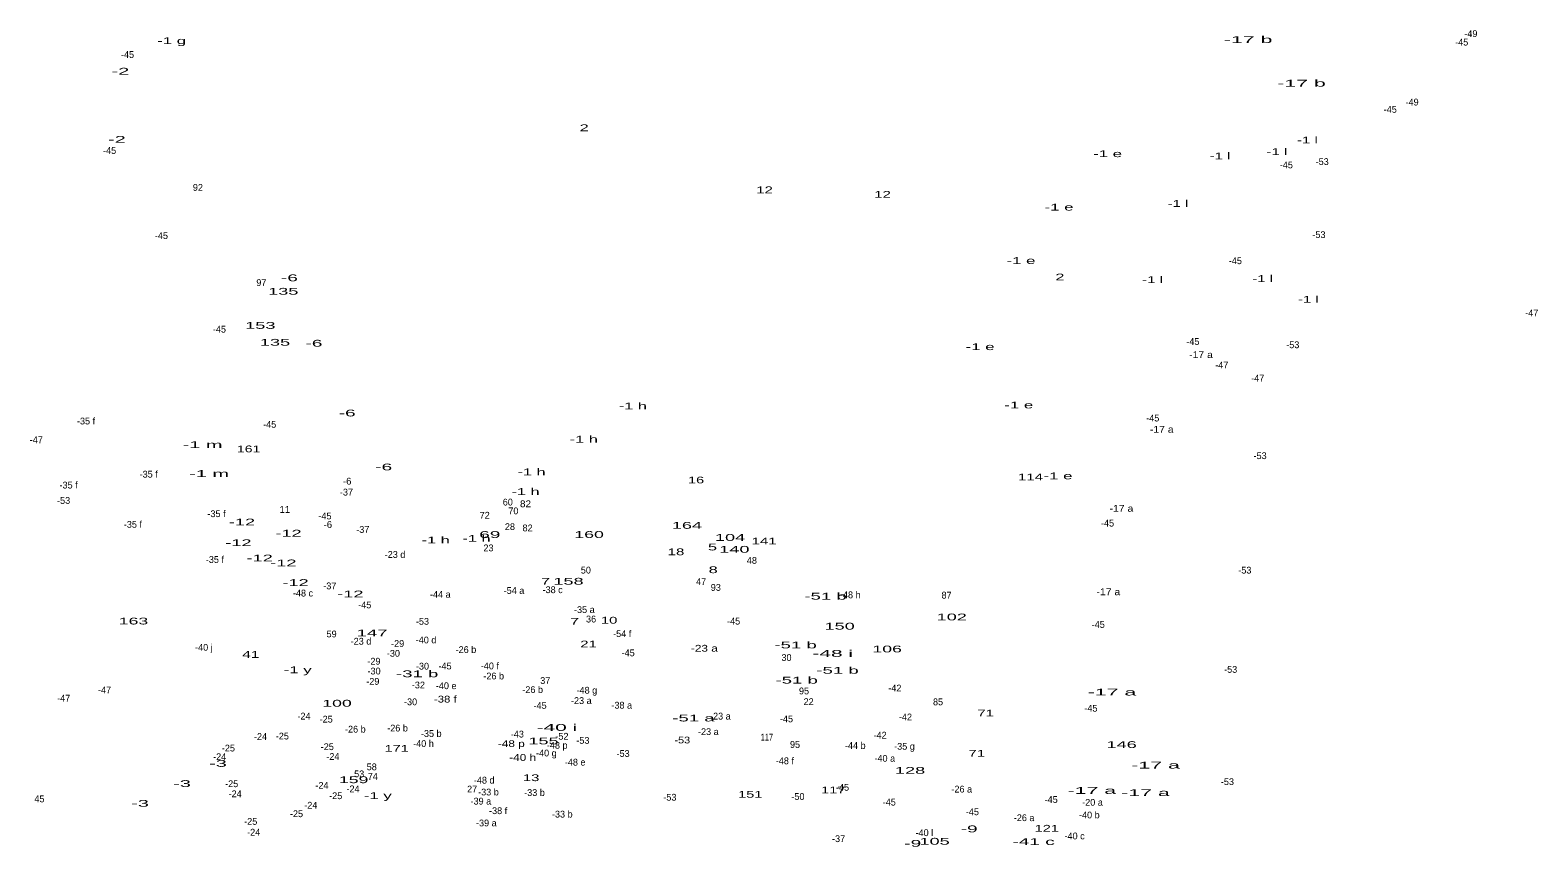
# Model space of a CAD drawing. Extents: x -668622 to -666786, y -990362 to -986505.
# Drawn here: x -667804 to -666915, y -988917 to -988436 of the extents above; entities that cross this region are included whole.
import ezdxf
from ezdxf.enums import TextEntityAlignment as Align

# ---------------------------------------------------------------- set-up
doc = ezdxf.new("R2010")
doc.units = 0
doc.header["$LTSCALE"] = 1.6
doc.layers.add('24', color=7, linetype='Continuous')

msp = doc.modelspace()

# ---------------------------------------------------------------- texts
at = {"layer": '24'}
for s, width, p in [('-1 g', 1.85, (-667720.401, -988444.19)), ('-17 b', 2.35, (-667085.535, -988443.52)), ('-2', 2.2, (-667750.564, -988462.18)), ('-17 b', 2.35, (-667054.045, -988469.23)), ('2', 1.8, (-667477.081, -988495.52)), ('-2', 2.2, (-667752.654, -988502.34)), ('-1 l', 1.65, (-667050.564, -988502.74)), ('-1 e', 1.85, (-667168.421, -988510.81)), ('-1 l', 1.65, (-667102.084, -988512.09)), ('-1 l', 1.65, (-667068.574, -988509.59)), ('12', 1.65, (-667370.707, -988532.11)), ('12', 1.65, (-667301.137, -988534.78)), ('-1 e', 1.85, (-667197.021, -988542.3)), ('-1 l', 1.65, (-667126.934, -988540.14)), ('-1 e', 1.85, (-667219.511, -988573.79)), ('-6', 2.1, (-667650.909, -988583.98)), ('2', 1.8, (-667196.541, -988583.49)), ('-1 l', 1.65, (-667141.914, -988585.04)), ('-1 l', 1.65, (-667077.014, -988584.4)), ('135', 2, (-667654.547, -988591.91)), ('-1 l', 1.65, (-667050.024, -988596.61)), ('153', 2, (-667668.077, -988612.03)), ('135', 2, (-667659.417, -988621.98)), ('-6', 2.1, (-667636.449, -988622.54)), ('-1 e', 1.85, (-667243.601, -988624.57)), ('-17 a', 1.15, (-667113.351, -988629.26)), ('-1 e', 1.85, (-667220.791, -988658.95)), ('-6', 2.1, (-667616.849, -988663.67)), ('-1 h', 1.8, (-667448.376, -988659.49)), ('-17 a', 1.15, (-667136.481, -988673.29)), ('-1 m', 2.2, (-667702.129, -988682.31)), ('161', 1.55, (-667674.979, -988684.82)), ('-1 h', 1.8, (-667477.286, -988679.09)), ('-1 m', 2.2, (-667698.279, -988699.34)), ('-6', 2.1, (-667595.329, -988695.48)), ('-1 h', 1.8, (-667508.136, -988698.37)), ('16', 1.6, (-667411.093, -988703.16)), ('114', 1.65, (-667213.859, -988701.35)), ('-1 e', 1.85, (-667197.661, -988700.73)), ('-6', 1.05, (-667616.84, -988703.84)), ('-1 h', 1.8, (-667511.666, -988709.94)), ('11', 1.05, (-667653.654, -988720.52)), ('82', 1.1, (-667511.679, -988717.19)), ('-17 a', 1.15, (-667160.25, -988719.88)), ('-12', 2, (-667678.911, -988727.94)), ('-6', 1.05, (-667628.25, -988729.38)), ('164', 2, (-667416.488, -988729.91)), ('-12', 2, (-667651.441, -988734.52)), ('-1 h', 1.8, (-667564.676, -988738.54)), ('-1 h', 1.8, (-667540.576, -988737.58)), ('69', 2.1, (-667532.751, -988735.31)), ('160', 1.95, (-667474.179, -988735.29)), ('104', 2, (-667391.049, -988737.03)), ('-12', 2, (-667681.001, -988740.15)), ('18', 1.65, (-667422.927, -988745.5)), ('5', 1.8, (-667401.401, -988742.68)), ('140', 2, (-667388.509, -988744.02)), ('141', 1.65, (-667370.959, -988739.14)), ('-12', 2, (-667668.471, -988749.15)), ('-12', 2, (-667654.491, -988752.04)), ('8', 1.8, (-667400.991, -988756.06)), ('-12', 2, (-667647.271, -988763.61)), ('7', 1.8, (-667499.866, -988762.86)), ('158', 2, (-667486.337, -988762.85)), ('-12', 2, (-667614.981, -988770.35)), ('-51 b', 2.05, (-667334.751, -988771.66)), ('-17 a', 1.15, (-667167.961, -988769.05)), ('163', 1.95, (-667742.873, -988786.31)), ('7', 1.8, (-667482.746, -988786.51)), ('10', 1.65, (-667462.394, -988785.81)), ('150', 2, (-667326.434, -988789.33)), ('102', 2, (-667260.314, -988783.91)), ('147', 2.05, (-667602.188, -988793.31)), ('21', 1.65, (-667474.537, -988799.86)), ('-51 b', 2.05, (-667352.421, -988800.42)), ('41', 1.7, (-667673.693, -988805.99)), ('-23 a', 1.3, (-667406.2, -988802.35)), ('-48 i', 2.3, (-667330.504, -988805.4)), ('106', 1.95, (-667298.409, -988802.78)), ('-1 y', 1.85, (-667646.041, -988815.04)), ('-31 b', 2.05, (-667575.591, -988817.41)), ('-51 b', 2.05, (-667327.681, -988815.36)), ('-51 b', 2.05, (-667351.771, -988821.15)), ('100', 1.95, (-667622.85, -988834.76)), ('-38 f', 1.25, (-667558.98, -988832.33)), ('-17 a', 2.35, (-667165.815, -988828.18)), ('-51 a', 2.05, (-667412.651, -988843.48)), ('71', 1.65, (-667240.343, -988840.57)), ('-40 i', 2.3, (-667493.187, -988849.04)), ('171', 1.6, (-667587.689, -988861.4)), ('-48 p', 1.3, (-667520.05, -988858.58)), ('155', 2, (-667501.067, -988856.99)), ('-53', 1.2, (-667419.22, -988856.44)), ('117', 0.8, (-667369.331, -988854.75)), ('146', 2, (-667160.138, -988859.13)), ('-3', 2.2, (-667693.054, -988870.23)), ('-40 h', 1.3, (-667513.35, -988866.71)), ('71', 1.65, (-667245.543, -988864.25)), ('-17 a', 2.35, (-667140.115, -988871.24)), ('159', 1.95, (-667613.033, -988879.86)), ('13', 1.65, (-667508.367, -988878.67)), ('128', 2, (-667284.907, -988874.36)), ('-3', 2.2, (-667714.254, -988882.11)), ('-1 y', 1.85, (-667598.811, -988889.2)), ('151', 1.6, (-667379.144, -988888.46)), ('117', 1.6, (-667330.209, -988885.87)), ('-17 a', 2.35, (-667177.695, -988886.18)), ('-17 a', 2.35, (-667146.055, -988887.47)), ('-3', 2.2, (-667739.004, -988893.76)), ('105', 2, (-667270.434, -988916.14)), ('-9', 2.1, (-667250.059, -988908.83)), ('-41 c', 2.1, (-667212.061, -988916.31)), ('121', 1.6, (-667204.264, -988908.47)), ('-9', 2.1, (-667283.309, -988917.35))]:
    msp.add_text(s, height=4, dxfattribs=dict(at, width=width)).set_placement(p, align=Align.CENTER)
for s, p in [('-45', (-666959.579, -988445.03)), ('-49', (-666954.175, -988440.03)), ('-45', (-667746.389, -988452.35)), ('-49', (-666988.835, -988480.39)), ('-45', (-667001.719, -988484.67)), ('-45', (-667756.949, -988508.9)), ('-53', (-667041.855, -988515.46)), ('-45', (-667062.999, -988517.41)), ('92', (-667704.883, -988530.68)), ('-45', (-667726.399, -988559.07)), ('-53', (-667043.775, -988558.52)), ('-45', (-667093.069, -988573.9)), ('97', (-667667.468, -988586.76)), ('-47', (-666918.275, -988604.69)), ('-45', (-667692.199, -988614.26)), ('-45', (-667118.129, -988621.52)), ('-53', (-667059.205, -988623.44)), ('-47', (-667101.075, -988635.37)), ('-47', (-667079.875, -988643.09)), ('-45', (-667141.779, -988666.63)), ('-35 f', (-667770.865, -988668.4)), ('-45', (-667662.559, -988670.35)), ('-47', (-667800.185, -988679.44)), ('-53', (-667078.475, -988688.83)), ('-35 f', (-667733.915, -988699.74)), ('-35 f', (-667781.145, -988706.16)), ('-37', (-667617.291, -988710.31)), ('-53', (-667784.085, -988715.21)), ('60', (-667522.127, -988716.19)), ('-35 f', (-667743.235, -988729.3)), ('-35 f', (-667693.925, -988723.03)), ('-45', (-667629.979, -988724.38)), ('72', (-667535.753, -988723.94)), ('70', (-667518.837, -988721.36)), ('-45', (-667168.449, -988728.59)), ('-37', (-667607.651, -988732.32)), ('28', (-667520.877, -988730.64)), ('82', (-667510.457, -988731.41)), ('-23 d', (-667588.633, -988747.06)), ('23', (-667533.537, -988743.18)), ('-35 f', (-667694.885, -988750.02)), ('50', (-667476.091, -988756.29)), ('48', (-667378.181, -988750.56)), ('-53', (-667087.475, -988756.31)), ('-37', (-667627.091, -988765.58)), ('47', (-667408.147, -988763.07)), ('-48 c', (-667642.897, -988769.82)), ('-44 a', (-667561.936, -988770.57)), ('-54 a', (-667518.472, -988768.32)), ('-38 c', (-667495.672, -988767.84)), ('93', (-667399.463, -988766.49)), ('-48 h', (-667320.162, -988770.86)), ('87', (-667263.373, -988771.04)), ('-45', (-667606.509, -988776.78)), ('-35 a', (-667476.993, -988779.57)), ('-53', (-667572.465, -988786.48)), ('36', (-667473.023, -988785.14)), ('-45', (-667388.959, -988786.36)), ('-45', (-667173.929, -988788.33)), ('59', (-667626.043, -988793.92)), ('-23 d', (-667608.713, -988798.21)), ('-29', (-667587.1, -988799.55)), ('-40 d', (-667570.345, -988797.46)), ('-54 f', (-667454.674, -988793.73)), ('-40 j', (-667701.338, -988801.8)), ('-29', (-667601.07, -988809.99)), ('-30', (-667589.589, -988805.33)), ('-26 b', (-667546.824, -988803.13)), ('-45', (-667451.149, -988805.06)), ('30', (-667357.781, -988807.82)), ('-30', (-667600.989, -988815.78)), ('-30', (-667572.449, -988812.91)), ('-45', (-667559.149, -988812.81)), ('-40 f', (-667532.717, -988812.75)), ('-26 b', (-667530.444, -988818.71)), ('-53', (-667095.825, -988814.8)), ('-47', (-667759.935, -988826.95)), ('-29', (-667601.72, -988821.88)), ('-32', (-667574.865, -988824)), ('-40 e', (-667558.455, -988824.45)), ('-26 b', (-667507.474, -988826.75)), ('37', (-667500.033, -988821.39)), ('-48 g', (-667475.487, -988827.09)), ('95', (-667347.443, -988827.5)), ('-42', (-667293.879, -988825.81)), ('-47', (-667784.035, -988831.77)), ('-30', (-667579.469, -988833.93)), ('-45', (-667503.089, -988836.07)), ('-23 a', (-667478.763, -988833.2)), ('-38 a', (-667454.933, -988835.93)), ('22', (-667344.717, -988833.82)), ('85', (-667268.407, -988833.96)), ('-24', (-667642.319, -988842.35)), ('-25', (-667629.235, -988844.15)), ('-23 a', (-667396.783, -988842.36)), ('-45', (-667357.779, -988843.99)), ('-42', (-667287.619, -988842.84)), ('-45', (-667178.259, -988837.72)), ('-24', (-667667.969, -988854.39)), ('-25', (-667655.095, -988854.11)), ('-26 b', (-667612.044, -988850.04)), ('-26 b', (-667587.144, -988849.4)), ('-35 b', (-667567.273, -988852.6)), ('-43', (-667516.499, -988852.96)), ('-52', (-667490.215, -988854.24)), ('-23 a', (-667403.853, -988851.51)), ('-42', (-667302.559, -988853.6)), ('-25', (-667686.905, -988861.18)), ('-25', (-667628.595, -988860.37)), ('-40 h', (-667571.85, -988858.52)), ('-48 p', (-667492.997, -988859.55)), ('-53', (-667477.845, -988856.66)), ('95', (-667352.753, -988859.07)), ('-44 b', (-667317.216, -988859.67)), ('-35 g', (-667288.183, -988860.15)), ('-24', (-667692.059, -988866.28)), ('-24', (-667625.289, -988866.13)), ('58', (-667602.367, -988872.26)), ('-40 g', (-667499.385, -988864.12)), ('-48 e', (-667482.397, -988869.51)), ('-53', (-667454.135, -988864.41)), ('-48 f', (-667358.73, -988868.71)), ('-40 a', (-667299.805, -988867.22)), ('53', (-667609.767, -988876.4)), ('74', (-667601.757, -988877.92)), ('-48 d', (-667536.047, -988880.11)), ('-53', (-667097.755, -988881)), ('-25', (-667684.975, -988882.22)), ('-24', (-667682.909, -988888.13)), ('-24', (-667631.719, -988883.16)), ('-25', (-667623.615, -988889.29)), ('-24', (-667613.409, -988885.25)), ('27', (-667543.173, -988885.37)), ('-33 b', (-667533.543, -988887.1)), ('-33 b', (-667506.393, -988887.42)), ('-53', (-667426.555, -988890.18)), ('-50', (-667351.039, -988889.75)), ('-45', (-667324.729, -988884.35)), ('-26 a', (-667254.424, -988885.38)), ('45', (-667798.351, -988891.13)), ('-24', (-667638.309, -988894.89)), ('-39 a', (-667538.014, -988892.48)), ('-38 f', (-667527.835, -988898.11)), ('-45', (-667297.169, -988893.05)), ('-45', (-667248.149, -988898.75)), ('-45', (-667201.699, -988891.5)), ('-20 a', (-667177.31, -988893.17)), ('-25', (-667673.735, -988904.4)), ('-25', (-667646.745, -988899.9)), ('-39 a', (-667534.794, -988905.34)), ('-33 b', (-667490.003, -988900.12)), ('-26 a', (-667217.634, -988902.25)), ('-40 b', (-667179.175, -988900.64)), ('-24', (-667671.989, -988910.79)), ('-37', (-667327.051, -988914.61)), ('-40 l', (-667276.462, -988911.08)), ('-40 c', (-667187.865, -988913.01))]:
    msp.add_text(s, height=4, dxfattribs=at).set_placement(p, align=Align.CENTER)

doc.saveas('drawing.dxf')
